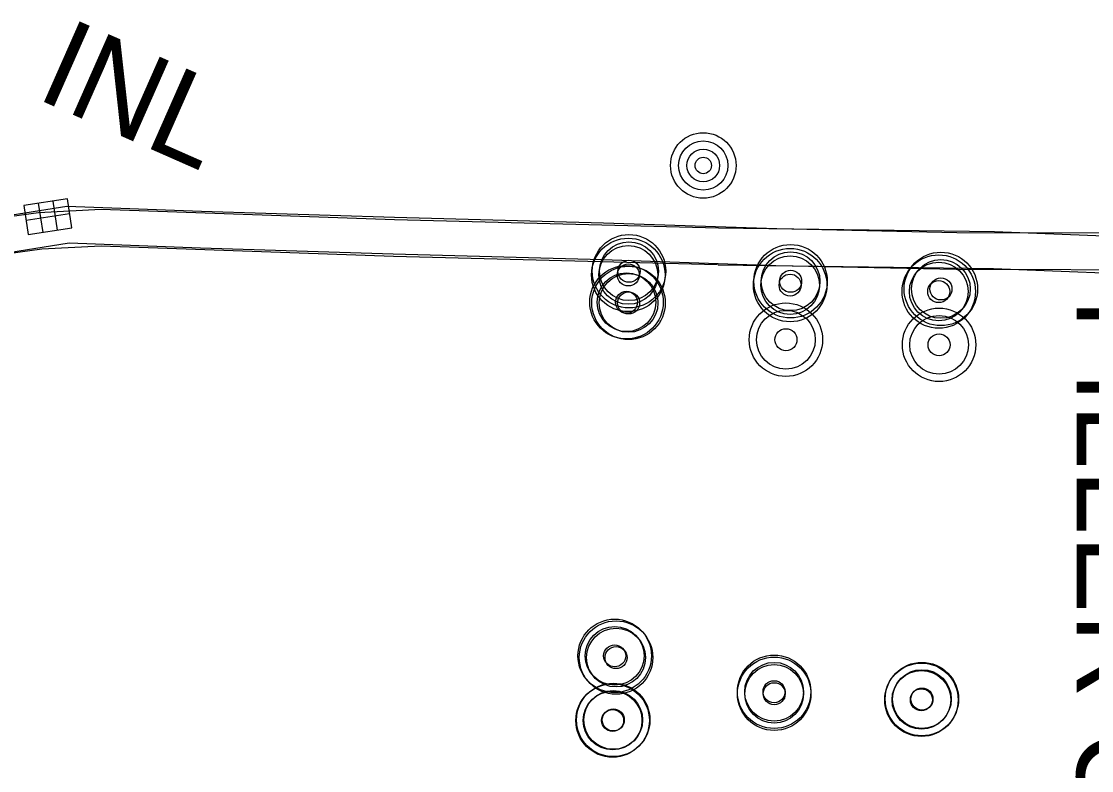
# Model space of a CAD drawing. Extents: x 588843 to 2552415, y 180129 to 269402.
# Drawn here: x 594553.8 to 594626.6, y 185042.3 to 185093.3 of the extents above; entities that cross this region are included whole.
import ezdxf

# ---------------------------------------------------------------- set-up
doc = ezdxf.new("R2010")
doc.units = 0
for name, color, linetype in [('Default', 7, 'Continuous'), ('E_DRN', 7, 'Continuous'), ('E_DRN_Text', 7, 'Continuous'), ('E_DWY', 7, 'Continuous'), ('E_MISCPROP', 7, 'Continuous'), ('E_MISCPROP_Text', 7, 'Continuous')]:
    doc.layers.add(name, color=color, linetype=linetype)

# ---------------------------------------------------------------- blocks, each defined once
blk = doc.blocks.new('INLO')
at = {"layer": 'E_DRN'}
for p, q in [((2, -4), (2, 0)), ((4, -4), (4, 0)), ((6, -2), (0, -2))]:
    blk.add_line(p, q, dxfattribs=at)
blk.add_lwpolyline([(0, -4), (6, -4), (6, 0), (0, 0), (0, -4)], close=True, dxfattribs=at)
blk = doc.blocks.new('INLT_50')
at = {"layer": 'E_DRN_Text'}
blk.add_text('INL', height=12, dxfattribs=at).set_placement((-11.03, -6))
blk = doc.blocks.new('FILO')
at = {"layer": 'E_MISCPROP'}
for radius in [5, 4, 1.5]:
    blk.add_circle((0, 0), radius, dxfattribs=at)
blk = doc.blocks.new('FILT_5')
at = {"layer": 'E_MISCPROP_Text'}
blk.add_text('FILLER CAPS', height=12, dxfattribs=at).set_placement((10, -6))
blk = doc.blocks.new('POLE')
at = {"layer": 'Default'}
for radius in [4.46, 3.35, 2.23, 1.12]:
    blk.add_circle((0, 0), radius, dxfattribs=at)
blk = doc.blocks.new('FILO_1')
at = {"layer": 'E_MISCPROP'}
for radius in [16.4, 13.12, 4.92]:
    blk.add_circle((0, 0), radius, dxfattribs=at)

msp = doc.modelspace()

# ---------------------------------------------------------------- linework, layer by layer
at = {"layer": 'E_DWY'}
for points in [[(594633.227, 185078.857), (594617.409, 185078.891), (594605.154, 185079.15), (594593.364, 185079.545), (594579.134, 185079.935), (594566.02, 185080.339), (594556.853, 185080.689), (594547.397, 185079.193), (594537.291, 185077.792), (594532.649, 185077.448), (594529.768, 185077.437), (594512.584, 185077.426), (594499.423, 185077.414), (594490.182, 185077.478)], [(594537.755, 185077.922), (594554.915, 185080.281), (594559.174, 185080.495), (594579.145, 185079.797), (594601.199, 185079.22)], [(594601.199, 185079.22), (594619.967, 185078.968), (594645.279, 185077.971), (594657.638, 185077.506), (594663.155, 185077.463), (594663.079, 185058.235)], [(594632.999, 185076.345), (594617.357, 185076.392), (594605.086, 185076.651), (594593.288, 185077.046), (594579.061, 185077.436), (594565.934, 185077.84), (594557.002, 185078.182), (594547.764, 185076.72), (594537.556, 185075.305), (594532.746, 185074.948), (594529.773, 185074.937), (594512.586, 185074.926), (594499.416, 185074.914), (594490.164, 185074.978)], [(594538.095, 185075.445), (594555.148, 185077.789), (594559.193, 185077.993), (594579.069, 185077.298), (594601.134, 185076.721)], [(594601.166, 185076.72), (594619.901, 185076.469), (594645.183, 185075.472), (594657.581, 185075.006), (594660.645, 185074.982), (594660.579, 185058.245)]]:
    msp.add_lwpolyline(points, dxfattribs=at)

# ---------------------------------------------------------------- block references
at = {"layer": 'E_DRN', "xscale": 0.5, "yscale": 0.5000000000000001, "rotation": -171.25286930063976}
msp.add_blockref('INLO', (594557.189, 185079.226), dxfattribs=at)
at = {"layer": 'E_DRN_Text', "xscale": 0.5, "yscale": 0.49999999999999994, "rotation": -23.815454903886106}
msp.add_blockref('INLT_50', (594560.874, 185088.614), dxfattribs=at)
at = {"layer": 'E_MISCPROP'}
for name, p, xscale, yscale, rotation in [('POLE', (594600.156, 185083.474), 0.4999999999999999, 0.49999999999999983, -22.695353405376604), ('FILO', (594595.101, 185076.274), 0.5, 0.49999999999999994, -23.815454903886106), ('FILO_1', (594595.054, 185076.021), 0.1524003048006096, 0.1524003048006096, -15.969778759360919), ('FILO', (594606.097, 185075.59), 0.5, 0.49999999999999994, -23.815454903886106), ('FILO_1', (594606.067, 185075.327), 0.1524003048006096, 0.1524003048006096, -15.969778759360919), ('FILO', (594616.325, 185075.068), 0.5, 0.49999999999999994, -23.815454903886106), ('FILO', (594595.071, 185074.115), 0.5, 0.49999999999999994, -23.815454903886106), ('FILO_1', (594616.181, 185074.89), 0.1524003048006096, 0.1524003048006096, -15.969778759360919), ('FILO_1', (594594.932, 185074.162), 0.1524003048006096, 0.1524003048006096, -15.969778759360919), ('FILO', (594605.779, 185071.611), 0.5, 0.49999999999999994, -23.815454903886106), ('FILO', (594616.203, 185071.262), 0.5, 0.49999999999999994, -23.815454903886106), ('FILO', (594594.128, 185050.084), 0.5, 0.49999999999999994, -23.815454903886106), ('FILO_1', (594594.22, 185049.967), 0.15240030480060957, 0.15240030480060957, -16.42604143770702), ('FILO', (594604.977, 185047.639), 0.5, 0.49999999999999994, -23.815454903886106), ('FILO_1', (594604.982, 185047.502), 0.15240030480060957, 0.15240030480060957, -16.42604143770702), ('FILO', (594615.034, 185047.142), 0.5, 0.49999999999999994, -23.815454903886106), ('FILO_1', (594615.002, 185047.092), 0.15240030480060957, 0.15240030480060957, -16.42604143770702), ('FILO', (594593.986, 185045.682), 0.5, 0.49999999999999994, -23.815454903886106), ('FILO_1', (594594.029, 185045.721), 0.15240030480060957, 0.15240030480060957, -16.42604143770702)]:
    msp.add_blockref(name, p, dxfattribs=dict(at, xscale=xscale, yscale=yscale, rotation=rotation))
at = {"layer": 'E_MISCPROP_Text', "xscale": 0.5, "yscale": 0.5, "rotation": -89.98949477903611}
msp.add_blockref('FILT_5', (594628.563, 185079.397), dxfattribs=at)

doc.saveas('drawing.dxf')
